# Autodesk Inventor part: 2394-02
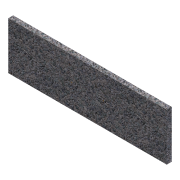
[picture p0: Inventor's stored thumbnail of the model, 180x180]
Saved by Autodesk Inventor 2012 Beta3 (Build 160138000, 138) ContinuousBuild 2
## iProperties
Created: 2011-02
Part Number: 2394-02
Material: Default
Document SubType Name: Modeling
Designer: Beta-8540w
Density: 1 g/cm^3
bottom_thickness: 0.130 in
Author: Beta-8540w
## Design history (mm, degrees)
sketch "Sketch1"
  geometry: L1 (-254, -76.2)-(254, -76.2); L2 (254, -76.2)-(254, 76.2); L3 (254, 76.2)-(-254, 76.2); L4 (-254, 76.2)-(-254, -76.2); 3 further points
  constraints: 8 end point, 2 midpoint, 2 parallel, 1 horizontal, 1 horizontal alignment, 1 perpendicular, 1 vertical alignment
  dimensions: "drawer_width" = 508 distance of L3.end L2.end; "drawer_height" = 152.4 distance of L2.end L1.end
extrude "Drawer Face" new body sketch "Sketch1" distance "d2" = 15.875; taper "d3" = 0 deg
sketch "Sketch2"
  geometry: 1 further point
hole "Single Hole Pull" sketch "Sketch2" at (0, 0) diameter "d4" = 4.4958; stored, may be unused: countersink angle "d8" = 82 deg, drill point angle "d10" = 118 deg; dims "d5" = 19.05, "d6" = 8.4328, "d7" = 6.35, "d9" = 25.4
sketch "Sketch3"
  geometry: L1 (-50.8, 0)-(50.8, 0); 2 further points
  constraints: 2 end point, 1 coincident, 1 horizontal, 1 midpoint
  dimensions: "dbl_pull_width" = 101.6 distance of L1.start L1.end
hole "Double Hole Pull" sketch "Sketch3" at (-50.8, 0), (50.8, 0) diameter "d12" = 4.4958; stored, may be unused: countersink angle "d16" = 82 deg, drill point angle "d18" = 118 deg; dims "d13" = 19.05, "d14" = 8.4328, "d15" = 6.35, "d17" = 25.4
sketch "Sketch4"
  geometry: L1 (254, -76.2)-(-254, -76.2) reference; L2 (254, 76.2)-(254, -76.2) reference; L3 (-254, 76.2)-(254, 76.2) reference; L4 (-254, -76.2)-(-254, 76.2) reference; L5 (-234.95, -72.898)-(-222.25, -72.898); L6 (-222.25, -72.898)-(-222.25, 72.898); L7 (-222.25, 72.898)-(-234.95, 72.898); L8 (-234.95, 72.898)-(-234.95, -72.898); L9 (222.25, 72.898)-(234.95, 72.898); L10 (234.95, 72.898)-(234.95, -72.898); L11 (234.95, -72.898)-(222.25, -72.898); L12 (222.25, -72.898)-(222.25, 72.898); 1 further point
  constraints: 16 end point, 4 parallel, 3 collinear, 2 horizontal, 2 perpendicular
  dimensions: "d72" = 19.05 distance between parallel lines of L4 L8; "d73" = 19.05 distance between parallel lines of L2 L10 (= d72); "d74" = 3.302 distance between parallel lines of L3 L9; "d75" = 3.302 distance between parallel lines of L1 L11 (= d74); "d76" = 12.7 distance of L9.start L9.end; "back_width" = 444.5 distance between parallel lines of L12 L6 (derived)
extrude "Side Relief" cut sketch "Sketch4" distance "d22" = 6.35; taper "d23" = 0 deg
sketch "Sketch5"
  geometry: L1 (254, -76.2)-(-254, -76.2) reference; L2 (-222.25, -66.548)-(222.25, -66.548); L3 (222.25, -66.548)-(222.25, -63.246); L4 (222.25, -63.246)-(-222.25, -63.246); L5 (-222.25, -63.246)-(-222.25, -66.548); L6 (-222.25, 72.898)-(-222.25, -72.898) reference; L7 (222.25, -72.898)-(222.25, 72.898) reference; 1 further point
  constraints: 8 end point, 2 parallel, 2 point on line, 1 horizontal, 1 perpendicular
  dimensions: "d24" = 9.652 distance between parallel lines of L1 L2; "bottom_thickness" = 3.302 distance of L2.end L3.end
extrude "Bottom Relief" cut sketch "Sketch5" distance "d26" = 6.35; taper "d27" = 0 deg
body "Solid1"
